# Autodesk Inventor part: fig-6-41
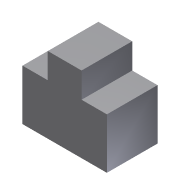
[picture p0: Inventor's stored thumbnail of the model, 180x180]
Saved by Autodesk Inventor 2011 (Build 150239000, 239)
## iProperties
Created: 2005-12
Part Number: fig-6-41
Document SubType Name: Modeling
Designer: CADCIM
Density: 1 g/cm^3
Author: CADCIM
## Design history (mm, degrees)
sketch "Sketch1"
  geometry: L1 (10, 15)-(25, 15); L2 (25, 15)-(25, -15); L3 (25, -15)-(-25, -15); L4 (-25, -15)-(-25, 15); L5 (-25, 15)-(-10, 15); L6 (10, 15)-(10, 30); L7 (10, 30)-(-10, 30); L8 (-10, 30)-(-10, 15)
  constraints: 16 end point, 3 parallel, 3 perpendicular, 2 equal length, 1 collinear, 1 horizontal
  dimensions: "d0" = 50 distance of L2.end L3.end; "d2" = 30 distance of L1.end L2.end; "d3" = 15 distance of L1.start L1.end; "d11" = 15 distance of L7.end L5.end
extrude "Extrusion1" new body sketch "Sketch1" stored distance "d7" = 30; taper "d8" = 0 deg
body "Solid1"
